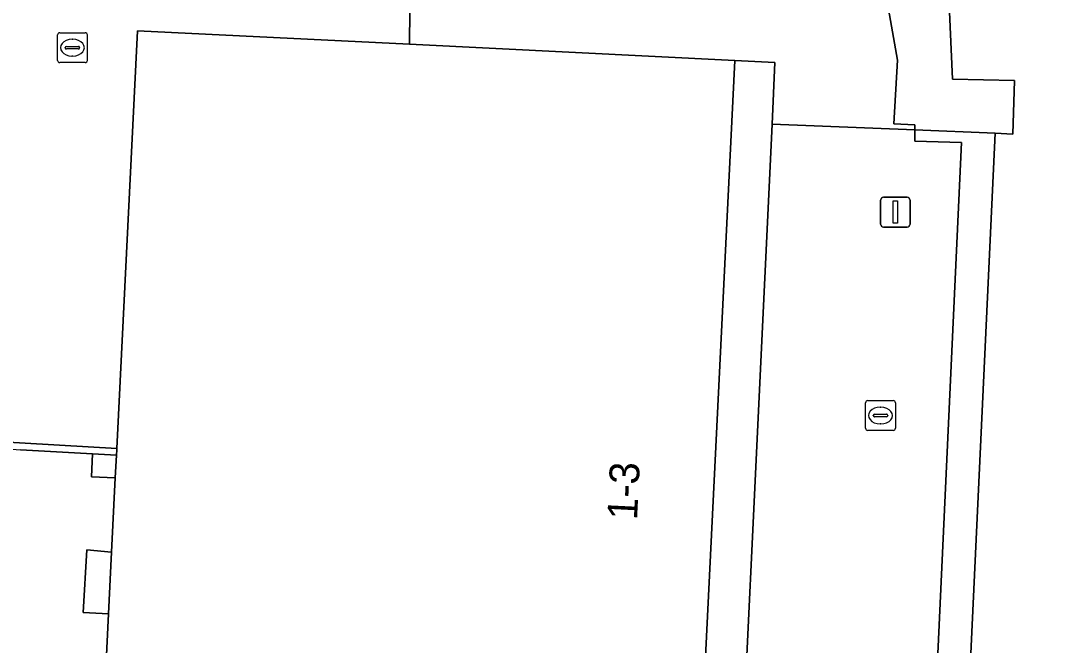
# Model space of a CAD drawing. Extents: x 161758 to 162722, y 384793 to 385405.
# Drawn here: x 162374.24 to 162408.86, y 385080.92 to 385101.88 of the extents above; entities that cross this region are included whole.
import ezdxf

# ---------------------------------------------------------------- set-up
doc = ezdxf.new("R2010")
doc.units = 0
for name, color, linetype in [('IMGEO_Groenvoorziening', 7, 'Continuous'), ('IMGEO_Haag', 7, 'Continuous'), ('IMGEO_Hek', 7, 'Continuous'), ('IMGEO_Kolk', 7, 'Continuous'), ('IMGEO_Lichtmast', 7, 'Continuous'), ('IMGEO_Loofbos', 7, 'Continuous'), ('IMGEO_Pand', 7, 'Continuous'), ('IMGEO_Pand_nummerreeks', 7, 'Continuous'), ('IMGEO_Rioolput', 7, 'Continuous'), ('IMGEO_Voetpad_open', 7, 'Continuous')]:
    doc.layers.add(name, color=color, linetype=linetype)

msp = doc.modelspace()

# ---------------------------------------------------------------- linework, layer by layer
at = {"layer": 'IMGEO_Groenvoorziening'}
msp.add_lwpolyline([(162402.944, 385104.629), (162403.666, 385100.554), (162403.541, 385098.416), (162404.25, 385098.383), (162404.247, 385098.213), (162406.946, 385098.102), (162407.536, 385098.075), (162407.59, 385099.872), (162405.506, 385099.92), (162405.19, 385107.198), (162407.287, 385109.447), (162408.471, 385113.399), (162408.538, 385116.438), (162406.588, 385116.444), (162406.601, 385116.303), (162406.612, 385116.162)], dxfattribs=at)
for points in [[(162405.822, 385074.201), (162406.946, 385098.102), (162404.247, 385098.213), (162404.241, 385097.842), (162405.806, 385097.791), (162404.495, 385069.287), (162405.588, 385069.236)], [(162377.464, 385087.529), (162373.415, 385087.759), (162373.407, 385087.54), (162373.496, 385087.535), (162374.232, 385087.489), (162376.647, 385087.355), (162377.453, 385087.31), (162377.462, 385087.485)], [(162377.453, 385087.31), (162376.647, 385087.355), (162376.616, 385086.583), (162377.415, 385086.541)], [(162377.292, 385084.054), (162376.465, 385084.124), (162376.338, 385082.032), (162377.19, 385081.987)]]:
    msp.add_lwpolyline(points, close=True, dxfattribs=at)
at = {"layer": 'IMGEO_Haag'}
msp.add_lwpolyline([(162402.944, 385104.629), (162403.666, 385100.554), (162403.541, 385098.416), (162404.25, 385098.383), (162404.247, 385098.213), (162406.946, 385098.102), (162407.536, 385098.075), (162407.59, 385099.872), (162405.506, 385099.92), (162405.19, 385107.198), (162407.287, 385109.447), (162408.471, 385113.399), (162408.538, 385116.438), (162406.588, 385116.444), (162406.601, 385116.303), (162406.612, 385116.162)], dxfattribs=at)
msp.add_lwpolyline([(162405.822, 385074.201), (162406.946, 385098.102), (162404.247, 385098.213), (162404.241, 385097.842), (162405.806, 385097.791), (162404.495, 385069.287), (162405.588, 385069.236)], close=True, dxfattribs=at)
at = {"layer": 'IMGEO_Hek'}
for points in [[(162387.301, 385102.223), (162387.283, 385101.087)], [(162404.247, 385098.213), (162399.452, 385098.409)], [(162406.946, 385098.102), (162404.247, 385098.213)], [(162405.822, 385074.201), (162406.946, 385098.102)]]:
    msp.add_lwpolyline(points, dxfattribs=at)
at = {"layer": 'IMGEO_Kolk'}
for p, q in [((162402.668, 385089.134), (162403.52, 385089.134)), ((162402.593, 385088.208), (162402.593, 385089.06)), ((162403.081, 385088.914), (162403.106, 385088.914)), ((162403.594, 385089.06), (162403.594, 385088.208)), ((162402.852, 385088.628), (162402.852, 385088.64)), ((162403.29, 385088.591), (162402.892, 385088.591)), ((162402.895, 385088.677), (162403.293, 385088.677)), ((162403.336, 385088.64), (162403.336, 385088.628)), ((162403.52, 385088.134), (162402.668, 385088.134)), ((162403.104, 385088.354), (162403.079, 385088.354))]:
    msp.add_line(p, q, dxfattribs=at)
for points in [[(162402.668, 385089.134), (162403.52, 385089.134)], [(162402.593, 385088.208), (162402.593, 385089.06)], [(162403.594, 385089.06), (162403.594, 385088.208)], [(162403.52, 385088.134), (162402.668, 385088.134)]]:
    msp.add_lwpolyline(points, dxfattribs=at)
for centre, radius, start, end in [((162402.67, 385089.058), 0.0765, 91.552, 178.448), ((162402.67, 385089.058), 0.0765, 91.552, 178.448), ((162403.518, 385089.058), 0.0765, 1.552, 88.448), ((162403.518, 385089.058), 0.0765, 1.552, 88.448), ((162402.892, 385088.637), 0.0403, 85.8775, 175.7526), ((162402.889, 385088.627), 0.0366, 178.938, 274.7102), ((162403.293, 385088.634), 0.043, 264.8664, 352.4533), ((162403.297, 385088.639), 0.0386, 1.7309, 96.639), ((162402.67, 385088.21), 0.0765, 181.552, 268.448), ((162402.67, 385088.21), 0.0765, 181.552, 268.448), ((162403.518, 385088.21), 0.0765, 271.552, 358.448), ((162403.518, 385088.21), 0.0765, 271.552, 358.448)]:
    msp.add_arc(centre, radius, start, end, dxfattribs=at)
for centre, major_axis, ratio, start_param, end_param in [((162403.08, 385088.634), (-0.387, 0.002), 0.722429, 4.712389, 7.853982), ((162403.105, 385088.634), (-0.39, 0.002), 0.717154, 1.570796, 4.712389)]:
    msp.add_ellipse(centre, major_axis=major_axis, ratio=ratio, start_param=start_param, end_param=end_param, dxfattribs=at)
at = {"layer": 'IMGEO_Lichtmast'}
for p, q in [((162403.097, 385095.057), (162403.097, 385095.857)), ((162403.097, 385095.857), (162403.097, 385095.057)), ((162403.197, 385095.957), (162403.987, 385095.957)), ((162403.987, 385095.957), (162403.197, 385095.957)), ((162404.087, 385095.857), (162404.087, 385095.057)), ((162404.087, 385095.057), (162404.087, 385095.857)), ((162403.987, 385094.957), (162403.197, 385094.957)), ((162403.197, 385094.957), (162403.987, 385094.957))]:
    msp.add_line(p, q, dxfattribs=at)
msp.add_lwpolyline([(162403.517, 385095.832), (162403.667, 385095.832), (162403.667, 385095.082), (162403.517, 385095.082), (162403.517, 385095.832)], dxfattribs=at)
for centre, start, end in [((162403.197, 385095.857), 90, 180), ((162403.197, 385095.857), 90, 180), ((162403.987, 385095.857), 0, 90), ((162403.987, 385095.857), 360, 90), ((162403.197, 385095.057), 180, 270), ((162403.197, 385095.057), 180, 270), ((162403.987, 385095.057), 270, 0), ((162403.987, 385095.057), 270, 0)]:
    msp.add_arc(centre, 0.1, start, end, dxfattribs=at)
at = {"layer": 'IMGEO_Loofbos'}
msp.add_lwpolyline([(162406.588, 385116.444), (162408.538, 385116.438), (162408.471, 385113.399), (162407.287, 385109.447), (162405.19, 385107.198), (162405.506, 385099.92), (162407.59, 385099.872), (162407.536, 385098.075), (162406.946, 385098.102), (162405.822, 385074.201)], dxfattribs=at)
at = {"layer": 'IMGEO_Pand'}
msp.add_lwpolyline([(162398.207, 385100.548), (162387.283, 385101.087), (162378.156, 385101.538), (162377.464, 385087.529), (162377.462, 385087.485), (162377.453, 385087.31), (162377.415, 385086.541), (162377.292, 385084.054), (162377.19, 385081.987), (162376.996, 385078.06), (162376.953, 385077.182), (162376.822, 385074.53), (162376.764, 385073.346), (162391.641, 385072.611), (162396.815, 385072.356)], close=True, dxfattribs=at)
at = {"layer": 'IMGEO_Rioolput'}
for p, q in [((162375.475, 385100.548), (162375.475, 385101.4)), ((162375.55, 385101.474), (162376.402, 385101.474)), ((162375.963, 385101.254), (162375.988, 385101.254)), ((162376.476, 385101.4), (162376.476, 385100.548)), ((162375.734, 385100.968), (162375.734, 385100.98)), ((162376.172, 385100.931), (162375.774, 385100.931)), ((162375.777, 385101.017), (162376.175, 385101.017)), ((162376.218, 385100.98), (162376.218, 385100.968)), ((162375.986, 385100.694), (162375.961, 385100.694)), ((162376.402, 385100.474), (162375.55, 385100.474))]:
    msp.add_line(p, q, dxfattribs=at)
for points in [[(162375.475, 385100.548), (162375.475, 385101.4)], [(162375.55, 385101.474), (162376.402, 385101.474)], [(162376.476, 385101.4), (162376.476, 385100.548)], [(162376.402, 385100.474), (162375.55, 385100.474)]]:
    msp.add_lwpolyline(points, dxfattribs=at)
for centre, radius, start, end in [((162375.552, 385101.398), 0.0765, 91.552, 178.448), ((162375.552, 385101.398), 0.0765, 91.552, 178.448), ((162376.4, 385101.398), 0.0765, 1.552, 88.448), ((162376.4, 385101.398), 0.0765, 1.552, 88.448), ((162375.774, 385100.977), 0.0403, 85.8775, 175.7526), ((162375.771, 385100.967), 0.0366, 178.938, 274.7102), ((162376.175, 385100.974), 0.043, 264.8664, 352.4533), ((162376.179, 385100.979), 0.0386, 1.7309, 96.639), ((162375.552, 385100.55), 0.0765, 181.552, 268.448), ((162375.552, 385100.55), 0.0765, 181.552, 268.448), ((162376.4, 385100.55), 0.0765, 271.552, 358.448), ((162376.4, 385100.55), 0.0765, 271.552, 358.448)]:
    msp.add_arc(centre, radius, start, end, dxfattribs=at)
for centre, major_axis, ratio, start_param, end_param in [((162375.962, 385100.974), (-0.387, 0.002), 0.722429, 4.712389, 7.853982), ((162375.987, 385100.974), (-0.39, 0.002), 0.717154, 1.570796, 4.712389)]:
    msp.add_ellipse(centre, major_axis=major_axis, ratio=ratio, start_param=start_param, end_param=end_param, dxfattribs=at)
at = {"layer": 'IMGEO_Voetpad_open'}
for points in [[(162390.439, 385113.294), (162390.719, 385113.485), (162388.121, 385113.605), (162388.104, 385113.266), (162387.895, 385113.277), (162387.725, 385110.167), (162387.405, 385104.322), (162387.301, 385102.223), (162387.283, 385101.087), (162398.207, 385100.548), (162399.551, 385100.482), (162399.452, 385098.409), (162404.247, 385098.213), (162404.25, 385098.383), (162403.541, 385098.416), (162403.666, 385100.554), (162402.944, 385104.629)], [(162373.415, 385087.759), (162377.464, 385087.529), (162378.156, 385101.538), (162387.283, 385101.087), (162387.301, 385102.223), (162374.244, 385102.765), (162374.402, 385106.118), (162378.278, 385110.648), (162368.747, 385111.133)], [(162395.555, 385016.551), (162399.452, 385098.409), (162399.551, 385100.482), (162398.207, 385100.548), (162396.815, 385072.356)], [(162376.996, 385078.06), (162377.19, 385081.987), (162376.338, 385082.032), (162376.465, 385084.124), (162377.292, 385084.054), (162377.415, 385086.541), (162376.616, 385086.583), (162376.647, 385087.355), (162374.232, 385087.489)]]:
    msp.add_lwpolyline(points, dxfattribs=at)
msp.add_lwpolyline([(162404.495, 385069.287), (162405.806, 385097.791), (162404.241, 385097.842), (162404.247, 385098.213), (162399.452, 385098.409), (162395.555, 385016.551), (162408.86, 385034.446), (162400.443, 385034.857), (162400.64, 385038.778), (162402.942, 385038.647), (162404.199, 385063.991), (162405.414, 385063.918), (162405.573, 385068.801), (162405.588, 385069.236)], close=True, dxfattribs=at)

# ---------------------------------------------------------------- texts
at = {"layer": 'IMGEO_Pand_nummerreeks'}
msp.add_text('1-3', height=1, rotation=87.1755, dxfattribs=at).set_placement((162394.922, 385085.119))

doc.saveas('drawing.dxf')
